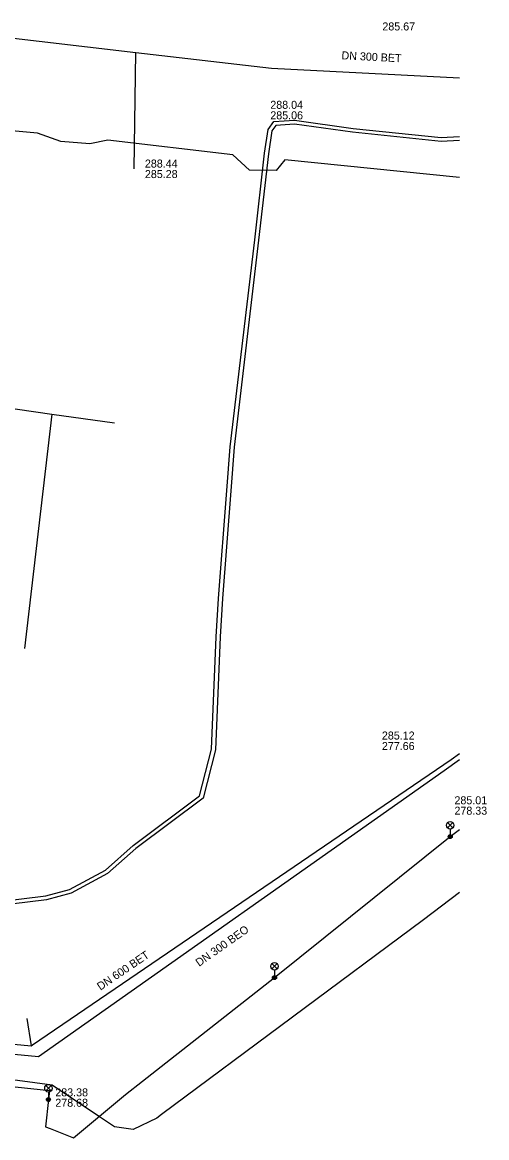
# Model space of a CAD drawing. Extents: x -595540 to -593988, y -1160850 to -1159202.
# Drawn here: x -594034.6 to -593988.1, y -1160271.8 to -1160160.3 of the extents above; entities that cross this region are included whole.
import ezdxf

# ---------------------------------------------------------------- set-up
doc = ezdxf.new("R2010")
doc.units = 0
for name, color, linetype in [('BVK-DESTOVA_popisy', 7, 'Continuous'), ('BVK-DESTOVA_trasa sítě', 7, 'Continuous'), ('BVK-SPLASKOVA_popisy', 7, 'Continuous'), ('BVK-SPLASKOVA_trasa sítě', 7, 'Continuous'), ('CETIN_kabel podzemní', 7, 'Continuous'), ('DESTOVA-NEPROVOZOVANA_popisy', 7, 'Continuous'), ('DESTOVA_trasa neprovozované sítě', 7, 'Continuous'), ('EON-NN_kabel', 7, 'Continuous'), ('TSB_kabel VO', 7, 'Continuous'), ('TSB_lampy VO', 7, 'Continuous')]:
    doc.layers.add(name, color=color, linetype=linetype)

msp = doc.modelspace()

# ---------------------------------------------------------------- linework, layer by layer
at = {"layer": 'BVK-DESTOVA_popisy'}
msp.add_line((-593998.6, -1160232.095), (-593998.6, -1160232.095), dxfattribs=at)
at = {"layer": 'BVK-DESTOVA_trasa sítě'}
msp.add_line((-593991.657, -1160233.96), (-593990.841, -1160233.374), dxfattribs=at)
for points in [[(-594033.678, -1160262.59), (-594033.532, -1160262.49), (-593991.657, -1160233.96)], [(-594064.562, -1160259.614), (-594062.166, -1160259.845), (-594042.226, -1160261.764), (-594040.802, -1160261.902), (-594040.656, -1160261.916), (-594033.678, -1160262.59)]]:
    msp.add_lwpolyline(points, dxfattribs=at)
at = {"layer": 'BVK-SPLASKOVA_popisy'}
for p, q in [((-593991.343, -1160237.641), (-593991.343, -1160237.641)), ((-594031.263, -1160266.828), (-594031.263, -1160266.828))]:
    msp.add_line(p, q, dxfattribs=at)
at = {"layer": 'BVK-SPLASKOVA_trasa sítě'}
for p, q in [((-593992.387, -1160235.068), (-593990.841, -1160233.967)), ((-594032.932, -1160263.639), (-593992.387, -1160235.068))]:
    msp.add_line(p, q, dxfattribs=at)
msp.add_lwpolyline([(-594066.147, -1160260.404), (-594043.773, -1160262.609), (-594042.053, -1160262.772), (-594032.932, -1160263.639)], dxfattribs=at)
at = {"layer": 'CETIN_kabel podzemní'}
for points in [[(-594042.413, -1160197.901), (-594031.594, -1160199.458)], [(-594031.594, -1160199.458), (-594034.35, -1160222.879)], [(-594031.594, -1160199.458), (-594025.33, -1160200.329)], [(-593990.841, -1160247.252), (-593994.43, -1160250), (-594020.63, -1160269.45), (-594021.1, -1160269.8), (-594023.46, -1160270.95), (-594025.34, -1160270.66), (-594026.84, -1160269.67), (-594031.59, -1160266.52), (-594037.3, -1160265.75)]]:
    msp.add_lwpolyline(points, dxfattribs=at)
at = {"layer": 'DESTOVA-NEPROVOZOVANA_popisy'}
for p, q in [((-594009.761, -1160169.994), (-594009.761, -1160169.994)), ((-594022.302, -1160175.863), (-594022.302, -1160175.863))]:
    msp.add_line(p, q, dxfattribs=at)
at = {"layer": 'DESTOVA_trasa neprovozované sítě'}
for p, q in [((-594023.361, -1160174.95), (-594023.208, -1160163.309)), ((-594009.641, -1160164.885), (-593990.841, -1160165.847)), ((-594034.122, -1160259.861), (-594033.678, -1160262.59))]:
    msp.add_line(p, q, dxfattribs=at)
msp.add_lwpolyline([(-594037.744, -1160161.621), (-594023.208, -1160163.309), (-594009.641, -1160164.885)], dxfattribs=at)
at = {"layer": 'EON-NN_kabel'}
for points in [[(-594041.177, -1160248.688), (-594032.225, -1160247.604), (-594029.839, -1160246.945), (-594026.259, -1160245.017), (-594023.468, -1160242.564), (-594016.835, -1160237.584), (-594015.633, -1160232.936), (-594015.189, -1160221.692), (-594014.938, -1160217.861), (-594014.103, -1160207.088), (-594013.769, -1160202.718), (-594011.323, -1160182.039), (-594010.348, -1160173.39), (-594009.978, -1160170.998), (-594009.424, -1160170.214), (-594007.331, -1160170.066), (-594001.481, -1160170.894), (-593992.673, -1160171.794), (-593990.841, -1160171.711)], [(-593990.841, -1160172.11), (-593992.685, -1160172.194), (-594001.529, -1160171.292), (-594007.345, -1160170.468), (-594009.206, -1160170.6), (-594009.598, -1160171.152), (-594009.952, -1160173.442), (-594010.925, -1160182.085), (-594013.371, -1160202.756), (-594013.705, -1160207.118), (-594014.54, -1160217.889), (-594014.789, -1160221.712), (-594015.235, -1160232.994), (-594016.483, -1160237.82), (-594023.216, -1160242.874), (-594026.029, -1160245.347), (-594029.689, -1160247.319), (-594032.147, -1160247.998), (-594041.149, -1160249.088)]]:
    msp.add_lwpolyline(points, dxfattribs=at)
at = {"layer": 'TSB_kabel VO'}
for points in [[(-593990.841, -1160175.808), (-594008.321, -1160174.044), (-594009.189, -1160175.093), (-594011.851, -1160175.073), (-594013.495, -1160173.53), (-594026.018, -1160172.077), (-594027.82, -1160172.457), (-594030.711, -1160172.22), (-594033.039, -1160171.374), (-594045.847, -1160170.221)], [(-594044.67, -1160265.68), (-594031.854, -1160267.032), (-594031.95, -1160267.944), (-594032.251, -1160270.659), (-594031.776, -1160270.825), (-594029.427, -1160271.759), (-594024.245, -1160267.458), (-594022.528, -1160266.108), (-594009.341, -1160255.758), (-593991.771, -1160241.668), (-593990.841, -1160240.945)]]:
    msp.add_lwpolyline(points, dxfattribs=at)
at = {"layer": 'TSB_lampy VO'}
for p, q in [((-593992.036, -1160240.808), (-593991.506, -1160240.278)), ((-593992.036, -1160240.278), (-593991.506, -1160240.808)), ((-593992.036, -1160240.808), (-593991.506, -1160240.278)), ((-593992.036, -1160240.278), (-593991.506, -1160240.808)), ((-593991.771, -1160240.918), (-593991.771, -1160241.668)), ((-593991.771, -1160240.918), (-593991.771, -1160241.668)), ((-594009.606, -1160254.898), (-594009.076, -1160254.368)), ((-594009.606, -1160254.368), (-594009.076, -1160254.898)), ((-594009.606, -1160254.898), (-594009.076, -1160254.368)), ((-594009.606, -1160254.368), (-594009.076, -1160254.898)), ((-594009.341, -1160255.008), (-594009.341, -1160255.758)), ((-594009.341, -1160255.008), (-594009.341, -1160255.758)), ((-594032.215, -1160267.084), (-594031.685, -1160266.554)), ((-594032.215, -1160266.554), (-594031.685, -1160267.084)), ((-594032.215, -1160267.084), (-594031.685, -1160266.554)), ((-594032.215, -1160266.554), (-594031.685, -1160267.084)), ((-594031.95, -1160267.194), (-594031.95, -1160267.944)), ((-594031.95, -1160267.194), (-594031.95, -1160267.944))]:
    msp.add_line(p, q, dxfattribs=at)
for centre, radius in [((-593991.771, -1160240.543), 0.375), ((-593991.771, -1160240.543), 0.375), ((-593991.771, -1160241.668), 0.2), ((-593991.771, -1160241.668), 0.2), ((-593991.771, -1160241.668), 0.145), ((-593991.771, -1160241.668), 0.145), ((-593991.771, -1160241.668), 0.0876), ((-593991.771, -1160241.668), 0.0876), ((-594009.341, -1160254.633), 0.375), ((-594009.341, -1160254.633), 0.375), ((-594009.341, -1160255.758), 0.2), ((-594009.341, -1160255.758), 0.2), ((-594009.341, -1160255.758), 0.145), ((-594009.341, -1160255.758), 0.145), ((-594009.341, -1160255.758), 0.0876), ((-594009.341, -1160255.758), 0.0876), ((-594031.95, -1160266.819), 0.375), ((-594031.95, -1160266.819), 0.375), ((-594031.95, -1160267.944), 0.2), ((-594031.95, -1160267.944), 0.2), ((-594031.95, -1160267.944), 0.145), ((-594031.95, -1160267.944), 0.145), ((-594031.95, -1160267.944), 0.0876), ((-594031.95, -1160267.944), 0.0876)]:
    msp.add_circle(centre, radius, dxfattribs=at)

# ---------------------------------------------------------------- texts
at = {"layer": 'BVK-DESTOVA_popisy'}
for s, p in [('285.12', (-593998.6, -1160231.97)), ('277.66', (-593998.6, -1160233.02))]:
    msp.add_text(s, height=0.8, dxfattribs=at).set_placement(p)
msp.add_text('DN 600 BET', height=0.8, rotation=34.26288, dxfattribs=at).set_placement((-594026.75, -1160257.075))
at = {"layer": 'BVK-SPLASKOVA_popisy'}
for s, p in [('285.67', (-593998.553, -1160161.11)), ('285.01', (-593991.343, -1160238.441)), ('278.33', (-593991.343, -1160239.481)), ('283.38', (-594031.263, -1160267.628)), ('278.68', (-594031.263, -1160268.668))]:
    msp.add_text(s, height=0.8, dxfattribs=at).set_placement(p)
msp.add_text('DN 300 BEO', height=0.8, rotation=35.17961, dxfattribs=at).set_placement((-594016.881, -1160254.696))
at = {"layer": 'DESTOVA-NEPROVOZOVANA_popisy'}
msp.add_text('DN 300 BET', height=0.8, rotation=357.0673, dxfattribs=at).set_placement((-594002.655, -1160163.99))
for s, p in [('288.04', (-594009.761, -1160168.944)), ('285.06', (-594009.761, -1160169.994)), ('288.44', (-594022.302, -1160174.813)), ('285.28', (-594022.302, -1160175.863))]:
    msp.add_text(s, height=0.8, dxfattribs=at).set_placement(p)

doc.saveas('drawing.dxf')
